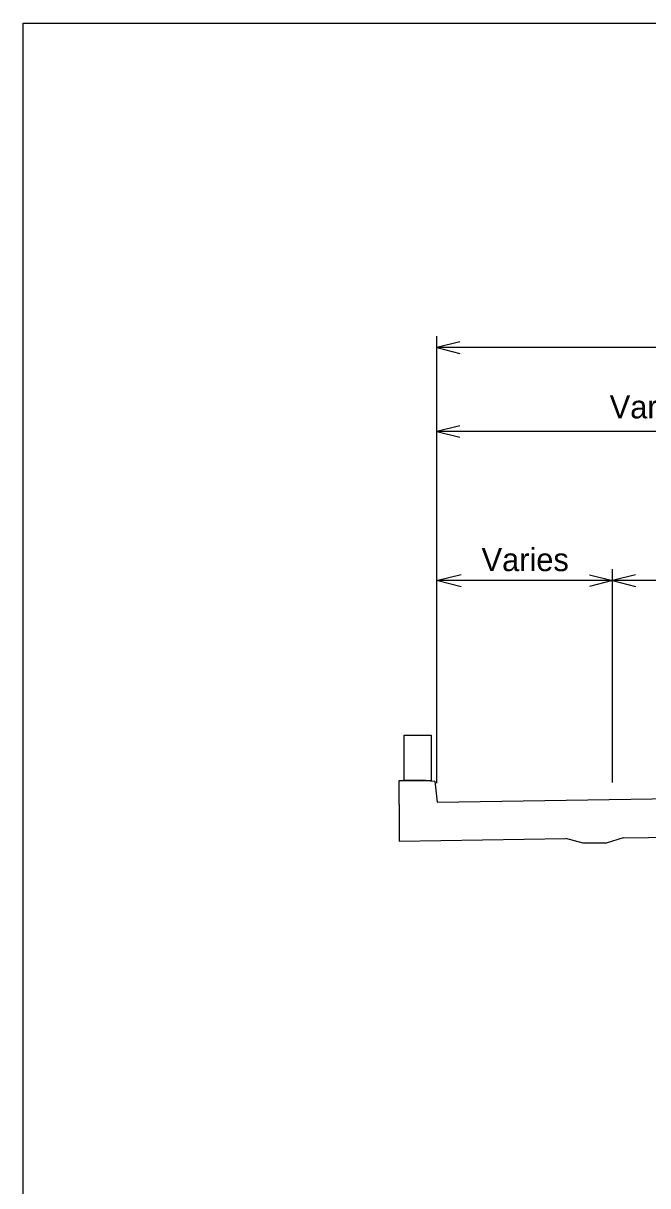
# Model space of a CAD drawing. Extents: x 10133 to 81668, y 7924 to 11018.
# Drawn here: x 10133 to 10675, y 8934 to 9944 of the extents above; entities that cross this region are included whole.
import ezdxf

# ---------------------------------------------------------------- set-up
doc = ezdxf.new("R2010")
doc.units = 0
for name, color, linetype in [('brgPreStructureExisting', 7, 'Continuous'), ('dsnStdLineDrawingWt2', 7, 'Continuous'), ('SheetBorder', 7, 'Continuous')]:
    doc.layers.add(name, color=color, linetype=linetype)

msp = doc.modelspace()

# ---------------------------------------------------------------- linework, layer by layer
at = {"layer": 'brgPreStructureExisting'}
for p, q in [((10482.5, 9286.2), (10463.8, 9286.2)), ((10487.1, 9285.7), (10482.5, 9286.2)), ((10492.3, 9267.4), (11122.5, 9276.9)), ((10459.2, 9265.4), (10459.2, 9233.4)), ((10459.2, 9233.4), (10604.2, 9235.6)), ((10654.2, 9236.3), (10764.2, 9238))]:
    msp.add_line(p, q, dxfattribs=at)
for points in [[(10463.8, 9286.2), (10463.8, 9325.4), (10487.1, 9325.4), (10487.1, 9285.7)], [(10463.8, 9286.2), (10463.8, 9325.4), (10487.1, 9325.4), (10487.1, 9285.7)], [(10459.2, 9265.4), (10459.2, 9286.2), (10482.5, 9286.2), (10490.4, 9285.4), (10492.3, 9267.4)], [(10654.2, 9236.3), (10639.2, 9231.8), (10619.2, 9231.8), (10604.2, 9235.6)]]:
    msp.add_lwpolyline(points, dxfattribs=at)
at = {"layer": 'dsnStdLineDrawingWt2'}
for p, q in [((10492.2, 9283.9), (10492.2, 9672.2)), ((11562.2, 9662.2), (10492.2, 9662.2)), ((11202.5, 9589.3), (10492.2, 9589.3)), ((10513.1, 9464.8), (10493.1, 9459.8)), ((10624.8, 9464.8), (10644.8, 9459.8)), ((10644.8, 9284.5), (10644.8, 9469.8)), ((10664.8, 9464.8), (10644.8, 9459.8)), ((11165.1, 9459.8), (10492.2, 9459.8)), ((10493.1, 9459.8), (10513.1, 9454.8)), ((10644.8, 9459.8), (10624.8, 9454.8)), ((10644.8, 9459.8), (10664.8, 9454.8))]:
    msp.add_line(p, q, dxfattribs=at)
for points in [[(10512.2, 9667.2), (10492.2, 9662.2), (10512.2, 9657.2)], [(10512.2, 9594.3), (10492.2, 9589.3), (10512.2, 9584.3)]]:
    msp.add_lwpolyline(points, dxfattribs=at)
at = {"layer": 'SheetBorder'}
msp.add_lwpolyline([(10132.5, 9944), (13267.5, 9944), (13267.5, 7924), (10132.5, 7924)], close=True, dxfattribs=at)

# ---------------------------------------------------------------- texts
at = {"layer": 'dsnStdLineDrawingWt2'}
for s, p in [("Varies: 41.08' to 34.33'", (10642.4, 9600.7)), ('Varies', (10531, 9468))]:
    msp.add_text(s, height=20, dxfattribs=at).set_placement(p)

doc.saveas('drawing.dxf')
